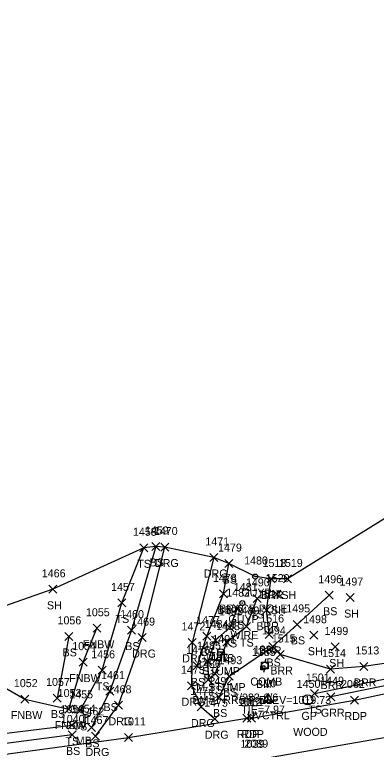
# Model space of a CAD drawing. Extents: x 1526508 to 1531550, y 369926 to 373082.
# Drawn here: x 1530976.9 to 1531067.4, y 370143.1 to 370326.7 of the extents above; entities that cross this region are included whole.
import ezdxf

# ---------------------------------------------------------------- set-up
doc = ezdxf.new("R2010")
doc.units = 0
for name, color, linetype in [('C_A', 7, 'Continuous'), ('C_C', 7, 'Continuous'), ('C_I', 7, 'Continuous'), ('CPBM', 7, 'Continuous'), ('CPSM', 7, 'Continuous'), ('L_A', 7, 'Continuous'), ('L_C', 7, 'Continuous'), ('L_I', 7, 'Continuous'), ('L_TIC', 7, 'Continuous'), ('LABL', 7, 'Continuous'), ('LELB', 7, 'Continuous'), ('LFNC', 7, 'Continuous'), ('LMB', 7, 'Continuous'), ('LSOGP', 7, 'Continuous'), ('LTS', 7, 'Continuous'), ('P_A', 7, 'Continuous'), ('P_I', 7, 'Continuous'), ('P_TIC', 7, 'Continuous'), ('PET', 7, 'Continuous'), ('PRC', 7, 'Continuous'), ('R_A', 7, 'Continuous'), ('R_C', 7, 'Continuous'), ('R_I', 7, 'Continuous'), ('R_TIC', 7, 'Continuous'), ('RDG', 7, 'Continuous'), ('RGP', 7, 'Continuous'), ('RGR', 7, 'Continuous'), ('U_A', 7, 'Continuous'), ('U_C', 7, 'Continuous'), ('U_I', 7, 'Continuous'), ('UP', 7, 'Continuous'), ('UPGW', 7, 'Continuous')]:
    doc.layers.add(name, color=color, linetype=linetype)

msp = doc.modelspace()

# ---------------------------------------------------------------- linework, layer by layer
at = {"layer": 'CPBM'}
for p, q in [((1531038.5, 370162.94), (1531038.5, 370163.94)), ((1531038.5, 370163.94), (1531039.5, 370163.94)), ((1531039.5, 370163.94), (1531039.5, 370162.94)), ((1531039.5, 370162.94), (1531038.5, 370162.94)), ((1531039.01, 370163.44), (1531039.01, 370163.44)), ((1531039.01, 370163.44), (1531039.01, 370163.44))]:
    msp.add_line(p, q, dxfattribs=at)
at = {"layer": 'CPSM'}
for p, q in [((1531039.15, 370154.88), (1531040.4, 370157.04)), ((1531041.65, 370154.88), (1531040.4, 370157.04)), ((1531040.4, 370155.6), (1531040.4, 370157.04)), ((1531039.15, 370154.88), (1531040.4, 370155.6)), ((1531039.15, 370154.88), (1531041.65, 370154.88)), ((1531040.4, 370155.6), (1531040.4, 370155.6)), ((1531040.4, 370155.6), (1531041.65, 370154.88))]:
    msp.add_line(p, q, dxfattribs=at)
at = {"layer": 'L_TIC'}
for points in [[(1531008.22, 370192.47), (1531010.22, 370194.47)], [(1531010.22, 370192.47), (1531008.22, 370194.47)], [(1531011.24, 370192.81), (1531013.24, 370194.81)], [(1531013.24, 370192.81), (1531011.24, 370194.81)], [(1531029.53, 370188.52), (1531031.53, 370190.52)], [(1531031.53, 370188.52), (1531029.53, 370190.52)], [(1531040.08, 370184.67), (1531042.08, 370186.67)], [(1531042.08, 370184.67), (1531040.08, 370186.67)], [(1531044.19, 370184.67), (1531046.19, 370186.67)], [(1531046.19, 370184.67), (1531044.19, 370186.67)], [(1530985.53, 370182.09), (1530987.53, 370184.09)], [(1530987.53, 370182.09), (1530985.53, 370184.09)], [(1531028.23, 370180.95), (1531030.23, 370182.95)], [(1531030.23, 370180.95), (1531028.23, 370182.95)], [(1531041.55, 370180.89), (1531043.55, 370182.89)], [(1531043.55, 370180.89), (1531041.55, 370182.89)], [(1531054.67, 370180.61), (1531056.67, 370182.61)], [(1531056.67, 370180.61), (1531054.67, 370182.61)], [(1531002.76, 370178.69), (1531004.76, 370180.69)], [(1531004.76, 370178.69), (1531002.76, 370180.69)], [(1531036.58, 370179.82), (1531038.58, 370181.82)], [(1531038.58, 370179.82), (1531036.58, 370181.82)], [(1531059.89, 370180.03), (1531061.89, 370182.03)], [(1531061.89, 370180.03), (1531059.89, 370182.03)], [(1531031.57, 370177.27), (1531033.57, 370179.27)], [(1531033.57, 370177.27), (1531031.57, 370179.27)], [(1531038.92, 370176.87), (1531040.92, 370178.87)], [(1531040.92, 370176.87), (1531038.92, 370178.87)], [(1531033.92, 370172.78), (1531035.92, 370174.78)], [(1531035.92, 370172.78), (1531033.92, 370174.78)], [(1531046.6, 370173.32), (1531048.6, 370175.32)], [(1531048.6, 370173.32), (1531046.6, 370175.32)], [(1530996.54, 370172.36), (1530998.54, 370174.36)], [(1530998.54, 370172.36), (1530996.54, 370174.36)], [(1531005.17, 370171.89), (1531007.17, 370173.89)], [(1531007.17, 370171.89), (1531005.17, 370173.89)], [(1531029.77, 370172.57), (1531031.77, 370174.57)], [(1531031.77, 370172.57), (1531029.77, 370174.57)], [(1530989.49, 370170.33), (1530991.49, 370172.33)], [(1530991.49, 370170.33), (1530989.49, 370172.33)], [(1531024.05, 370170.39), (1531026.05, 370172.39)], [(1531026.05, 370170.39), (1531024.05, 370172.39)], [(1531026.18, 370169.42), (1531028.18, 370171.42)], [(1531028.18, 370169.42), (1531026.18, 370171.42)], [(1531039.58, 370170.81), (1531041.58, 370172.81)], [(1531041.58, 370170.81), (1531039.58, 370172.81)], [(1531050.81, 370170.62), (1531052.81, 370172.62)], [(1531052.81, 370170.62), (1531050.81, 370172.62)], [(1531029.04, 370168.89), (1531031.04, 370170.89)], [(1531031.04, 370168.89), (1531029.04, 370170.89)], [(1531040.51, 370167.82), (1531042.51, 370169.82)], [(1531042.51, 370167.82), (1531040.51, 370169.82)], [(1531056.16, 370167.68), (1531058.16, 370169.68)], [(1531058.16, 370167.68), (1531056.16, 370169.68)], [(1531042.41, 370165.8), (1531044.41, 370167.8)], [(1531044.41, 370165.8), (1531042.41, 370167.8)], [(1530993.12, 370163.89), (1530995.12, 370165.89)], [(1530995.12, 370163.89), (1530993.12, 370165.89)], [(1531024.28, 370164.04), (1531026.28, 370166.04)], [(1531026.28, 370164.04), (1531024.28, 370166.04)], [(1530997.85, 370161.85), (1530999.85, 370163.85)], [(1530999.85, 370161.85), (1530997.85, 370163.85)], [(1531021.59, 370162.94), (1531023.59, 370164.94)], [(1531023.59, 370162.94), (1531021.59, 370164.94)], [(1531054.99, 370162.16), (1531056.99, 370164.16)], [(1531056.99, 370162.16), (1531054.99, 370164.16)], [(1531063.33, 370162.81), (1531065.33, 370164.81)], [(1531065.33, 370162.81), (1531063.33, 370164.81)], [(1531026.14, 370160.99), (1531028.14, 370162.99)], [(1531028.14, 370160.99), (1531026.14, 370162.99)], [(1531029.64, 370160.38), (1531031.64, 370162.38)], [(1531031.64, 370160.38), (1531029.64, 370162.38)], [(1531024.32, 370159.45), (1531026.32, 370161.45)], [(1531026.32, 370159.45), (1531024.32, 370161.45)], [(1530999.72, 370156.65), (1531001.72, 370158.65)], [(1531001.72, 370156.65), (1530999.72, 370158.65)], [(1530978.51, 370154.65), (1530980.51, 370156.65)], [(1530980.51, 370154.65), (1530978.51, 370156.65)], [(1530986.58, 370154.93), (1530988.58, 370156.93)], [(1530988.58, 370154.93), (1530986.58, 370156.93)], [(1531027.13, 370155.18), (1531029.13, 370157.18)], [(1531029.13, 370155.18), (1531027.13, 370157.18)], [(1531051, 370156.05), (1531053, 370158.05)], [(1531053, 370156.05), (1531051, 370158.05)], [(1530989.48, 370152.17), (1530991.48, 370154.17)], [(1530991.48, 370152.17), (1530989.48, 370154.17)], [(1530992.29, 370151.84), (1530994.29, 370153.84)], [(1530994.29, 370151.84), (1530992.29, 370153.84)], [(1530990.24, 370148.13), (1530992.24, 370150.13)], [(1530992.24, 370148.13), (1530990.24, 370150.13)], [(1530995.15, 370147.59), (1530997.15, 370149.59)], [(1530997.15, 370147.59), (1530995.15, 370149.59)], [(1530990.34, 370145.7), (1530992.34, 370147.7)], [(1530992.34, 370145.7), (1530990.34, 370147.7)]]:
    msp.add_lwpolyline(points, dxfattribs=at)
at = {"layer": 'LABL'}
for points in [[(1531157.87, 370185.93), (1531113.66, 370174.66), (1531094.82, 370170.61), (1531079.75, 370166.09), (1531064.33, 370163.81), (1531055.99, 370163.16), (1531043.41, 370166.8)], [(1531040.58, 370171.81), (1531039.92, 370177.87), (1531041.08, 370185.67)]]:
    msp.add_lwpolyline(points, dxfattribs=at)
at = {"layer": 'LELB'}
for points in [[(1530993.29, 370152.84), (1530998.85, 370162.85), (1531003.76, 370179.69), (1531009.22, 370193.47)], [(1531012.24, 370193.81), (1531006.17, 370172.89), (1531000.72, 370157.65), (1530996.15, 370148.59)], [(1531052, 370157.05), (1531071.33, 370161.04), (1531088.5, 370164.53), (1531103.99, 370168.65), (1531126.82, 370174.37), (1531147.94, 370179.24), (1531175.97, 370188.19), (1531192.8, 370192.85)], [(1531022.59, 370163.94), (1531025.05, 370171.39), (1531029.23, 370181.95), (1531030.53, 370189.52)], [(1531032.57, 370178.27), (1531030.77, 370173.57), (1531027.18, 370170.42), (1531025.28, 370165.04), (1531025.32, 370160.45), (1531027.14, 370161.99), (1531030.04, 370169.89), (1531034.92, 370173.78), (1531037.58, 370180.82)], [(1531028.13, 370156.18), (1531030.64, 370161.38), (1531041.51, 370168.82), (1531047.6, 370174.32), (1531055.67, 370181.61)], [(1530990.49, 370171.33), (1530987.58, 370155.93)], [(1530883.54, 370125.84), (1530896.12, 370129.31), (1530911.8, 370134.99), (1530934.8, 370141.1), (1530961.14, 370145.47), (1530991.24, 370149.13)], [(1530991.34, 370146.7), (1530961.31, 370142.81), (1530935.97, 370139.44), (1530906.69, 370130.9), (1530888.23, 370124.76)]]:
    msp.add_lwpolyline(points, dxfattribs=at)
at = {"layer": 'LFNC'}
msp.add_lwpolyline([(1530971.44, 370160.23), (1530979.51, 370155.65), (1530990.48, 370153.17), (1530994.12, 370164.89), (1530997.54, 370173.36)], dxfattribs=at)
at = {"layer": 'LMB'}
for p, q in [((1530994.57, 370151.87), (1530995.86, 370151.49)), ((1530994.58, 370149.28), (1530994.58, 370151.87)), ((1530994.58, 370150.97), (1530995.86, 370151.48)), ((1530993.92, 370149.27), (1530993.92, 370149.27))]:
    msp.add_line(p, q, dxfattribs=at)
msp.add_circle((1530993.92, 370149.27), 0.656, dxfattribs=at)
at = {"layer": 'LSOGP'}
msp.add_lwpolyline([(1531177.54, 370326.67), (1531158.16, 370311.5), (1531136.38, 370307.37), (1531128.26, 370297.45), (1531117.26, 370278.94), (1531108.22, 370270.78), (1531090.84, 370249.56), (1531076.08, 370230.71), (1531079.53, 370219.46), (1531075.62, 370215.22), (1531071.94, 370202.31), (1531045.19, 370185.67), (1531041.08, 370185.67), (1531037.14, 370186.29), (1531030.53, 370189.52), (1531026.78, 370191.04), (1531014.55, 370193.66), (1531012.24, 370193.81), (1531009.22, 370193.47), (1530986.53, 370183.09), (1530962.18, 370174.64)], dxfattribs=at)
at = {"layer": 'LTS'}
for p, q in [((1531027.69, 370167.79), (1531027.69, 370166.12)), ((1531029.36, 370167.62), (1531029.36, 370167.79)), ((1531029.36, 370167.79), (1531029.36, 370166.12)), ((1531028.52, 370166.65), (1531028.52, 370166.65)), ((1531028.52, 370166.65), (1531028.52, 370166.65)), ((1531028.52, 370166.62), (1531028.52, 370166.62))]:
    msp.add_line(p, q, dxfattribs=at)
msp.add_circle((1531028.52, 370166.65), 0.0833, dxfattribs=at)
for centre, start, end in [((1531026.86, 370166.12), 270, 360), ((1531030.19, 370166.12), 180, 270)]:
    msp.add_arc(centre, 0.833, start, end, dxfattribs=at)
msp.add_ellipse((1531028.52, 370167.79), major_axis=(-0.833, 0), ratio=0.5, dxfattribs=at)
at = {"layer": 'P_TIC'}
for points in [[(1531060.97, 370154.43), (1531062.97, 370156.43)], [(1531062.97, 370154.43), (1531060.97, 370156.43)], [(1531033.99, 370149.93), (1531035.99, 370151.93)], [(1531035.99, 370149.93), (1531033.99, 370151.93)], [(1531035.19, 370149.91), (1531037.19, 370151.91)], [(1531037.19, 370149.91), (1531035.19, 370151.91)], [(1531004.44, 370145.08), (1531006.44, 370147.08)], [(1531006.44, 370145.08), (1531004.44, 370147.08)]]:
    msp.add_lwpolyline(points, dxfattribs=at)
at = {"layer": 'PET'}
for points in [[(1531036.19, 370150.91), (1531061.97, 370155.43), (1531104.8, 370164.58), (1531143.1, 370174.02), (1531180.11, 370184.91), (1531218.48, 370196.81), (1531260.06, 370210.9), (1531302.03, 370225.36), (1531352.57, 370243.2), (1531401.62, 370260.1), (1531448.12, 370277.05), (1531486.93, 370290.59), (1531531.91, 370306.21)], [(1530659.86, 369987.59), (1530689.68, 370004.88), (1530725.77, 370025.63), (1530760.95, 370046.59), (1530789.35, 370063.64), (1530821.52, 370083.59), (1530847.47, 370098.66), (1530877.57, 370115.25), (1530907.84, 370128.26), (1530938.81, 370136.76), (1530967.77, 370140.97), (1531005.44, 370146.08), (1531034.99, 370150.93)], [(1531036.19, 370150.91), (1531034.99, 370150.93)]]:
    msp.add_lwpolyline(points, dxfattribs=at)
at = {"layer": 'PRC'}
msp.add_lwpolyline([(1531037.76, 370140.53), (1531081.39, 370148.17), (1531130.61, 370160.04), (1531176.3, 370172.81), (1531216.72, 370185.49), (1531265.37, 370201.61), (1531315.14, 370219.14), (1531364.47, 370236.54), (1531403.01, 370250.24), (1531441.26, 370263.86), (1531484.78, 370279.08), (1531519.83, 370291.48), (1531535.78, 370296.89)], dxfattribs=at)
at = {"layer": 'R_TIC'}
for points in [[(1531013.55, 370192.66), (1531015.55, 370194.66)], [(1531015.55, 370192.66), (1531013.55, 370194.66)], [(1531025.78, 370190.04), (1531027.78, 370192.04)], [(1531027.78, 370190.04), (1531025.78, 370192.04)], [(1531007.85, 370170.03), (1531009.85, 370172.03)], [(1531009.85, 370170.03), (1531007.85, 370172.03)], [(1531020.38, 370168.83), (1531022.38, 370170.83)], [(1531022.38, 370168.83), (1531020.38, 370170.83)], [(1531020.22, 370157.99), (1531022.22, 370159.99)], [(1531022.22, 370157.99), (1531020.22, 370159.99)], [(1531055.08, 370155.26), (1531057.08, 370157.26)], [(1531057.08, 370155.26), (1531055.08, 370157.26)], [(1531001.95, 370153.11), (1531003.95, 370155.11)], [(1531003.95, 370153.11), (1531001.95, 370155.11)], [(1531022.57, 370152.69), (1531024.57, 370154.69)], [(1531024.57, 370152.69), (1531022.57, 370154.69)], [(1531026.03, 370149.76), (1531028.03, 370151.76)], [(1531028.03, 370149.76), (1531026.03, 370151.76)], [(1530996.19, 370145.43), (1530998.19, 370147.43)], [(1530998.19, 370145.43), (1530996.19, 370147.43)]]:
    msp.add_lwpolyline(points, dxfattribs=at)
at = {"layer": 'RDG'}
for points in [[(1530997.19, 370146.43), (1531002.95, 370154.11), (1531008.85, 370171.03), (1531014.55, 370193.66)], [(1531026.78, 370191.04), (1531021.38, 370169.83), (1531021.22, 370158.99), (1531023.57, 370153.69), (1531027.03, 370150.76)]]:
    msp.add_lwpolyline(points, dxfattribs=at)
at = {"layer": 'RGP'}
msp.add_line((1531050.27, 370155.47), (1531050.27, 370155.47), dxfattribs=at)
for radius in [1.25, 0.0833]:
    msp.add_circle((1531050.27, 370155.47), radius, dxfattribs=at)
at = {"layer": 'RGR'}
msp.add_lwpolyline([(1531193.3, 370191.46), (1531163.03, 370182.34), (1531135.13, 370174.16), (1531103.13, 370167.28), (1531088.75, 370162.91), (1531056.08, 370156.26)], dxfattribs=at)
at = {"layer": 'UP'}
for p, q in [((1531039.76, 370165.7), (1531039.51, 370164.87)), ((1531038.68, 370163.2), (1531038.68, 370164.87)), ((1531038.68, 370164.87), (1531040.34, 370164.87)), ((1531039.51, 370164.04), (1531039.51, 370164.04)), ((1531040.34, 370164.87), (1531040.34, 370163.2)), ((1531040.34, 370163.2), (1531038.68, 370163.2)), ((1531039.26, 370162.37), (1531039.51, 370163.2))]:
    msp.add_line(p, q, dxfattribs=at)
msp.add_circle((1531039.51, 370164.04), 0.833, dxfattribs=at)
at = {"layer": 'UPGW'}
for centre, radius in [((1531037.14, 370186.29), 0.625), ((1531037.14, 370186.29), 0.0833), ((1531033.9, 370179.66), 0.625), ((1531033.9, 370179.66), 0.0833)]:
    msp.add_circle(centre, radius, dxfattribs=at)

# ---------------------------------------------------------------- texts
at = {"layer": 'C_A'}
for s, p in [('BM', (1531037.32, 370158.44)), ('HVCTRL', (1531035.09, 370150.6))]:
    msp.add_text(s, height=2, dxfattribs=at).set_placement(p)
at = {"layer": 'C_C'}
msp.add_text('BM#1 RRSIP ELEV=1019.73', height=2, dxfattribs=at).set_placement((1531021.4, 370154.44))
at = {"layer": 'C_I'}
for s, p in [('1385', (1531036.31, 370166.44)), ('10', (1531039.41, 370158.6))]:
    msp.add_text(s, height=2, dxfattribs=at).set_placement(p)
at = {"layer": 'L_A'}
for s, p in [('TS', (1531007.63, 370188.47)), ('BS', (1531010.69, 370188.81)), ('BS', (1531028.98, 370184.52)), ('BRR', (1531038.57, 370180.67)), ('SH', (1531043.68, 370180.67)), ('SH', (1530985.02, 370178.09)), ('BS', (1531027.67, 370176.95)), ('SH', (1531041.04, 370176.89)), ('BS', (1531054.11, 370176.61)), ('TS', (1531002.17, 370174.69)), ('TS', (1531035.99, 370175.82)), ('SH', (1531059.38, 370176.03)), ('TS', (1531030.98, 370173.27)), ('BRR', (1531037.41, 370172.87)), ('BS', (1531046.04, 370169.32)), ('FNBW', (1530994.01, 370168.36)), ('BS', (1531004.61, 370167.89)), ('TS', (1531029.18, 370168.57)), ('TS', (1531033.33, 370168.78)), ('BS', (1530988.93, 370166.33)), ('BS', (1531023.49, 370166.39)), ('TS', (1531025.59, 370165.42)), ('BRR', (1531038.07, 370166.81)), ('SH', (1531050.3, 370166.62)), ('TS', (1531028.45, 370164.89)), ('BS', (1531039.95, 370163.82)), ('SH', (1531055.65, 370163.68)), ('BRR', (1531040.9, 370161.8)), ('FNBW', (1530990.59, 370159.89)), ('TS', (1531023.69, 370160.04)), ('STUMP', (1531023.94, 370161.65)), ('BS', (1531021.03, 370158.94)), ('BRR', (1531053.48, 370158.16)), ('BRR', (1531061.82, 370158.81)), ('TS', (1530997.26, 370157.85)), ('TS', (1531025.55, 370156.99)), ('BS', (1531029.08, 370156.38)), ('TS', (1531023.73, 370155.45)), ('BS', (1530999.16, 370152.65)), ('BS', (1530986.02, 370150.93)), ('BS', (1531026.57, 370151.18)), ('TS', (1531050.41, 370152.05)), ('FNBW', (1530975.99, 370150.65)), ('FNBW', (1530986.95, 370148.17)), ('TS', (1530991.7, 370147.84)), ('TS', (1530989.65, 370144.13)), ('MB', (1530992.23, 370144.27)), ('BS', (1530994.59, 370143.59)), ('BS', (1530989.78, 370141.7))]:
    msp.add_text(s, height=2, dxfattribs=at).set_placement(p)
at = {"layer": 'L_C'}
msp.add_text('M.STUMP', height=2, dxfattribs=at).set_placement((1531022.38, 370157.65))
at = {"layer": 'L_I'}
for s, p in [('1459', (1531009.54, 370196.81)), ('1458', (1531006.53, 370196.47)), ('1479', (1531027.83, 370192.52)), ('1518', (1531038.96, 370188.67)), ('1519', (1531043.06, 370188.67)), ('1466', (1530983.73, 370186.09)), ('1478', (1531026.54, 370184.95)), ('1490', (1531034.8, 370183.82)), ('1520', (1531039.77, 370184.89)), ('1496', (1531052.92, 370184.61)), ('1497', (1531058.2, 370184.03)), ('1457', (1531001.06, 370182.69)), ('1482', (1531029.88, 370181.27)), ('1517', (1531037.79, 370180.87)), ('1055', (1530994.77, 370176.36)), ('1483', (1531028.07, 370176.57)), ('1489', (1531032.22, 370176.78)), ('1495', (1531044.9, 370177.32)), ('1460', (1531003.34, 370175.89)), ('1516', (1531038.4, 370174.81)), ('1498', (1531049.12, 370174.62)), ('1056', (1530987.66, 370174.33)), ('1477', (1531022.36, 370174.39)), ('1484', (1531024.49, 370173.42)), ('1488', (1531027.34, 370172.89)), ('1494', (1531038.82, 370171.82)), ('1499', (1531054.46, 370171.68)), ('1491', (1531026.39, 370169.65)), ('1515', (1531041.28, 370169.8)), ('1054', (1530991.35, 370167.89)), ('1485', (1531022.59, 370168.04)), ('1456', (1530996.1, 370165.85)), ('1476', (1531019.84, 370166.94)), ('1514', (1531053.87, 370166.16)), ('1513', (1531062.21, 370166.81)), ('1487', (1531024.44, 370164.99)), ('1493', (1531027.94, 370164.38)), ('1486', (1531022.57, 370163.45)), ('1461', (1530998.55, 370160.65)), ('1501', (1531049.8, 370160.05)), ('1052', (1530976.74, 370158.65)), ('1057', (1530984.8, 370158.93)), ('1492', (1531025.44, 370159.18)), ('1053', (1530987.71, 370156.17)), ('1455', (1530990.6, 370155.84)), ('1050', (1530988.38, 370152.13)), ('1454', (1530991.23, 370152.27)), ('1462', (1530993.41, 370151.59)), ('1040', (1530988.48, 370149.7))]:
    msp.add_text(s, height=2, dxfattribs=at).set_placement(p)
at = {"layer": 'P_A'}
for p in [(1531059.46, 370150.43), (1531032.48, 370145.93), (1531033.68, 370145.91)]:
    msp.add_text('RDP', height=2, dxfattribs=at).set_placement(p)
at = {"layer": 'P_I'}
for s, p in [('2062', (1531058.59, 370158.43)), ('1012', (1531032.79, 370153.93)), ('2061', (1531033.37, 370153.91)), ('1011', (1531003.81, 370149.08)), ('1039', (1531033.44, 370143.48)), ('2089', (1531034.42, 370143.53))]:
    msp.add_text(s, height=2, dxfattribs=at).set_placement(p)
at = {"layer": 'R_A'}
for s, p in [('DRG', (1531012.04, 370188.66)), ('DRG', (1531024.27, 370186.04)), ('DRG', (1531006.34, 370166.03)), ('DRG', (1531018.87, 370164.83)), ('DRG', (1531018.71, 370153.99)), ('GRR', (1531053.56, 370151.26)), ('DRG', (1531000.43, 370149.11)), ('GP', (1531048.7, 370150.47)), ('DRG', (1531021.05, 370148.69)), ('DRG', (1531024.52, 370145.76)), ('DRG', (1530994.68, 370141.43))]:
    msp.add_text(s, height=2, dxfattribs=at).set_placement(p)
at = {"layer": 'R_C'}
msp.add_text('WOOD', height=2, dxfattribs=at).set_placement((1531046.62, 370146.47))
at = {"layer": 'R_I'}
for s, p in [('1470', (1531011.77, 370196.66)), ('1471', (1531024.65, 370194.04)), ('1469', (1531006.11, 370174.03)), ('1472', (1531018.69, 370172.83)), ('1473', (1531018.53, 370161.99)), ('1450', (1531047.49, 370158.47)), ('1449', (1531053.38, 370159.26)), ('1468', (1531000.21, 370157.11)), ('1474', (1531020.87, 370156.69)), ('1475', (1531024.34, 370153.76)), ('1467', (1530994.45, 370149.43))]:
    msp.add_text(s, height=2, dxfattribs=at).set_placement(p)
at = {"layer": 'U_A'}
for s, p in [('GUYP', (1531033.66, 370181.29)), ('GUYP', (1531030.41, 370174.66)), ('COMB', (1531035.89, 370159.04))]:
    msp.add_text(s, height=2, dxfattribs=at).set_placement(p)
at = {"layer": 'U_C'}
for s, p in [('BRACE POLE', (1531028.1, 370177.29)), ('WIRE', (1531030.93, 370170.66)), ('7/283-6/6', (1531031.58, 370155.04)), ('TIE=7.97', (1531033.64, 370152.04))]:
    msp.add_text(s, height=2, dxfattribs=at).set_placement(p)
at = {"layer": 'U_I'}
for s, p in [('1480', (1531034.36, 370189.29)), ('1481', (1531031.77, 370182.66)), ('1386', (1531036.76, 370167.04))]:
    msp.add_text(s, height=2, dxfattribs=at).set_placement(p)

doc.saveas('drawing.dxf')
